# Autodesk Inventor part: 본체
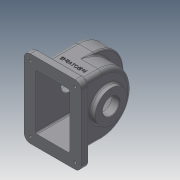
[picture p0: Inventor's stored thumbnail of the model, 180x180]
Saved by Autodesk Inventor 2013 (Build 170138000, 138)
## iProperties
Created: 2017-11
Part Number: 본체
Material: 일반
Document SubType Name: Modeling
Designer: Administrator
Density: 1 g/cm^3
Author: Administrator
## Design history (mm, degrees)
sketch "스케치1"
  geometry: L1 (55, -75)-(-55, -75); L2 (-55, -75)-(-55, 75); L3 (-55, 75)-(55, 75); L4 (55, 75)-(55, -75); 3 further points
  constraints: 8 end point, 2 midpoint, 2 parallel, 1 horizontal, 1 horizontal alignment, 1 perpendicular, 1 vertical alignment
  dimensions: "d0" = 110 distance of L1.start L1.end; "d2" = 150 distance of L3.end L1.start
extrude "돌출1" new body sketch "스케치1" distance "d3" = 15; taper "d4" = 0 deg
node "작업 평면1"
sketch "스케치2"
  geometry: L1 (-73.548, 80)-(207.715, 80); L2 (-87.984, 144)-(207.715, 144); L3 (0, 0)-(150, 0) reference; L4 (17, 0)-(17, 80); L5 (133, 80)-(133, 0); L6 (17, 0)-(133, 0); A1 r 58 centre (75, 80) between (133, 80) and (17, 80); 3 further points
  constraints: 10 end point, 4 point on line, 3 perpendicular, 2 midpoint, 2 point on circle, 2 tangent, 1 centre point, 1 coincident, 1 horizontal, 1 parallel
  dimensions: "d6" = 80 distance from line of L1.start L3; "d7" = 144 distance from line of L2.start L3; "d8" = 58 radius of A1
extrude "돌출2" join sketch "스케치2" distance "d9" = 38; taper "d10" = 0 deg
sketch "스케치3"
  geometry: L1 (-133, 15)-(-17, 15) reference; L2 (-133, 15)-(-133, 80) reference; L3 (-17, 80)-(-17, 15) reference; L4 (-133, 15)-(-133, 57); L5 (-17, 57)-(-17, 15); L6 (-133, 15)-(-17, 15); L7 (-150, 0)-(0, 0) reference; A1 r 58 centre (-75, 80) between (-17, 80) and (-133, 80) reference; A2 r 58 centre (-75, 57) between (-17, 57) and (-133, 57); 2 further points
  constraints: 6 end point, 3 point on circle, 2 point on line, 2 tangent, 1 centre point, 1 collinear, 1 parallel, 1 perpendicular, 1 vertical alignment
  dimensions: "d11" = 58 radius of A2; "d12" = 57 distance from line of A2.centre L7
extrude "돌출3" join sketch "스케치3" distance "d13" = 38; taper "d14" = 0 deg
sketch "스케치4"
  geometry: L1 (-133, 57)-(-133, 15) reference; L2 (-17, 15)-(-133, 15) reference; L3 (-17, 15)-(-17, 57) reference; L4 (-162.838, 65)-(17.703, 65); L5 (-75, 115)-(-75, 15); L6 (-150, 0)-(0, 0) reference; C1 r 31 at (-75, 65); A1 r 58 centre (-75, 57) between (-17, 57) and (-133, 57) reference; 1 further point
  constraints: 4 end point, 2 midpoint, 1 centre point, 1 perpendicular, 1 point on circle
  dimensions: "d15" = 65 distance from line of L4.start L6; "d16" = 62 diameter of C1
extrude "돌출4" join sketch "스케치4" distance "d17" = 10; taper "d18" = 0 deg
sketch "스케치5"
  geometry: C1 r 31 at (75, 65) reference; C2 r 37.5 at (75, 65); 1 further point
  constraints: 1 centre point, 1 coincident
  dimensions: "d19" = 75 diameter of C2
extrude "돌출5" join sketch "스케치5" distance "d21" = 9; taper "d22" = 0 deg
node "작업 평면2"
sketch "스케치6"
  geometry: L1 (133, 15)-(150, 15) reference; L2 (150, 15)-(150, 0) reference; L3 (150, 0)-(0, 0) reference; L4 (0, 0)-(0, 15) reference; L5 (0, 15)-(17, 15) reference; L6 (17, 15)-(17, 80) reference; L7 (133, 80)-(133, 15) reference; L8 (22, 80)-(22, 0); L9 (128, 80)-(128, 0); L10 (128, 0)-(22, 0); A1 r 58 centre (75, 80) between (133, 80) and (17, 80) reference; A2 r 53 centre (75, 80) between (128, 80) and (22, 80); 1 further point
  constraints: 6 end point, 2 perpendicular, 2 point on circle, 2 point on line, 2 tangent, 1 centre point, 1 coincident, 1 collinear
  dimensions: "d24" = 106 diameter of A2
extrude "돌출6" cut sketch "스케치6" distance "d26" = 28; taper "d27" = 0 deg
node "작업 평면3"
sketch "스케치7"
  geometry: L1 (-17, 15)-(0, 15) reference; L2 (0, 15)-(0, 0) reference; L3 (0, 0)-(-150, 0) reference; L4 (-150, 0)-(-150, 15) reference; L5 (-150, 15)-(-133, 15) reference; L6 (-133, 15)-(-133, 57) reference; L7 (-17, 57)-(-17, 15) reference; L8 (-128, 57)-(-128, 0); L9 (-22, 57)-(-22, 0); L10 (-22, 0)-(-128, 0); A1 r 58 centre (-75, 57) between (-17, 57) and (-133, 57) reference; A2 r 53 centre (-75, 57) between (-22, 57) and (-128, 57); 1 further point
  constraints: 6 end point, 2 perpendicular, 2 point on circle, 2 point on line, 2 tangent, 1 centre point, 1 coincident, 1 collinear
  dimensions: "d30" = 106 diameter of A2
extrude "돌출7" cut sketch "스케치7" distance "d32" = 38.25; taper "d33" = 0 deg
hole "구멍1" diameter "d36" = 32; stored, may be unused: countersink angle "d40" = 90 deg, drill point angle "d42" = 118 deg; dims "d34" = 10, "d35" = 10, "d37" = 6, "d38" = 4, "d39" = 2, "d41" = 8
sketch "스케치8"
  geometry: L1 (-75, -50)-(75, -50) reference; L2 (75, -50)-(75, -65) reference; L3 (75, -65)-(-75, -65) reference; L4 (-75, -65)-(-75, -50) reference; C1 r 16 at (0, 0) reference; C2 r 37.5 at (0, 0) reference; A1 r 29 centre (0, 0) between (0, 29) and (-29, 0); 3 further points
  constraints: 4 point on circle, 1 centre point, 1 coincident
  dimensions: "d43" = 58 diameter of A1
hole "구멍2" sketch "스케치8" at (0, 29), (-29, 0), (0, -29), (29, 0) diameter "d45" = 2.459; stored, may be unused: countersink angle "d49" = 90 deg, drill point angle "d51" = 118 deg; dims "d46" = 6, "d47" = 4, "d48" = 2, "d50" = 8
sketch "스케치9"
  geometry: L1 (-75, -50)-(75, -50) reference; L2 (75, -50)-(75, -65) reference; L3 (75, -65)-(-75, -65) reference; L4 (-75, -65)-(-75, -50) reference; C1 r 16 at (0, 0) reference; C2 r 31 at (0, 0) reference; A1 r 26 centre (0, 0) between (0, 26) and (-26, 0); 3 further points
  constraints: 4 point on circle, 1 centre point, 1 coincident
  dimensions: "d52" = 52 diameter of A1
hole "구멍3" sketch "스케치9" at (0, 26), (-26, 0), (0, -26), (26, 0) diameter "d54" = 2.459; stored, may be unused: countersink angle "d58" = 90 deg, drill point angle "d60" = 118 deg; dims "d55" = 6, "d56" = 4, "d57" = 2, "d59" = 8
node "작업 평면4"
sketch "스케치10"
  geometry: L1 (38, -58)-(38, 58) reference; C1 r 6 at (19, 0); 1 further point
  constraints: 1 centre point, 1 horizontal alignment
  dimensions: "d62" = 12 diameter of C1; "d64" = 19 distance from line of C1.centre L1
extrude "돌출8" join sketch "스케치10" distance "d65" = 7; taper "d66" = 0 deg
hole "구멍4" diameter "d69" = 4.134; stored, may be unused: countersink angle "d73" = 90 deg, drill point angle "d75" = 118 deg; dims "d70" = 6, "d71" = 4, "d72" = 2, "d74" = 8, "d76" = 10, "d77" = 10
fillet "모깎기1" dims "d78" = 12
hole "구멍5" diameter "d81" = 5; stored, may be unused: countersink angle "d85" = 90 deg, drill point angle "d87" = 118 deg; dims "d79" = 10, "d80" = 10, "d82" = 6, "d83" = 12, "d84" = 5, "d86" = 8
fillet "모깎기2" dims "d88" = 8
fillet "모깎기3" dims "d89" = 3
chamfer "모따기1" distance "d90" = 1; stored, may be unused: second distance "d91" = 2, angle "d92" = 45 deg
sketch "스케치11"
  geometry: L1 (4.455, 34.95)-(55.545, 34.95); L2 (55.545, 34.95)-(55.545, 9.05); L3 (55.545, 9.05)-(4.455, 9.05); L4 (4.455, 9.05)-(4.455, 34.95); L5 (73, -18)-(-13, -18) reference; L6 (-8, 62)-(-8, 0) reference; 3 further points
  constraints: 2 midpoint, 2 other
  dimensions: "d93" = 40 distance from line of point (4.455, 22) L5; "d94" = 38 distance from line of point (30, 34.95) L6
feature "엠보싱1" sketch "스케치11" dims "d0" = 110, "d2" = 150, "d95" = 0.5, "d96" = 0
node "솔리드1"
mirror "대칭1"
mirror "대칭2"
node "투영된 루프1"
node "투영된 루프2"
node "투영된 루프3"
node "절단 모서리 투영1"
node "절단 모서리 투영2"
node "절단 모서리 투영3"
node "절단 모서리 투영4"
other parameters: "d5" = -55, "d23" = 5, "d29" = -5, "d61" = 144
